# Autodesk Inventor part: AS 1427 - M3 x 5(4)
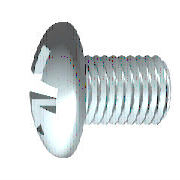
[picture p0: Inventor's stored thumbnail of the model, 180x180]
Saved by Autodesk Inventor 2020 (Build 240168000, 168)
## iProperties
Created: 2019-01
Part Number: AS 1427 - M3 x 5(4)
Material: Acier, doux
Description: Pozidriv Vis mécaniques métriques ISO
Document SubType Name: Modeling
Standard: AS 1427
Designer: bruno
Standards Organization: AS
Language: fr-FR
Size Designation: M3 x 5
Categories: <MemberInstance><Categories><Category DisplayName="Visserie" InternalName="e4da775c-781d-43d5-af7c-5136215cf5a6" Mnemonic="FSTN"><Category DisplayName="Vis" Int
Density: 7.85 g/cm^3
Appearance: Semi-poli
IsCustomPart: 0
Author: bruno
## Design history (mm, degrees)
body "Solid1"
workplane "Work Plane3"
sketch "Esquisse2"
  geometry: L1 (-4.2, 0)-(4.2, 0) reference; L2 (0, -4.2)-(0, 4.2) reference; L3 (0, 1.575)-(0, 0); L4 (0, 0)-(1.575, 0); L5 (0, 0)-(2.121, 2.121); L6 (0.35, 1.536)-(0.281, 0.474); L7 (1.536, 0.35)-(0.474, 0.281); L8 (0.35, -1.536)-(0.281, -0.474); L9 (1.536, -0.35)-(0.474, -0.281); L10 (-0.35, 1.536)-(-0.281, 0.474); L11 (-1.536, 0.35)-(-0.474, 0.281); L12 (-1.536, -0.35)-(-0.474, -0.281); L13 (-0.35, -1.536)-(-0.281, -0.474); A1 r 0.473 centre (0, 0) between (0.473, 0) and (0, 0.473); A2 r 1.575 centre (0, 0) between (1.575, 0) and (1.536, 0.35); A3 r 1.575 centre (0, 0) between (0.35, 1.536) and (0, 1.575); A4 r 1.575 centre (0, 0) between (1.536, 0.35) and (0.35, 1.536); A5 r 1.575 centre (0, 0) between (0, -1.575) and (0.35, -1.536); A6 r 1.575 centre (0, 0) between (0.35, -1.536) and (1.536, -0.35); A7 r 1.575 centre (0, 0) between (1.536, -0.35) and (1.575, 0); A8 r 1.575 centre (0, 0) between (-1.536, 0.35) and (-1.575, 0); A9 r 1.575 centre (0, 0) between (-0.35, 1.536) and (-1.536, 0.35); A10 r 1.575 centre (0, 0) between (0, 1.575) and (-0.35, 1.536); A11 r 1.575 centre (0, 0) between (-1.575, 0) and (-1.536, -0.35); A12 r 1.575 centre (0, 0) between (-1.536, -0.35) and (-0.35, -1.536); A13 r 1.575 centre (0, 0) between (-0.35, -1.536) and (0, -1.575); A14 r 0.551 centre (0, 0) between (0.551, 0) and (0, 0.551); A15 r 0.181 centre (0.462, 0.462) between (0.281, 0.474) and (0.474, 0.281); A16 r 0.181 centre (0.462, -0.462) between (0.474, -0.281) and (0.281, -0.474); A17 r 0.181 centre (-0.462, 0.462) between (-0.474, 0.281) and (-0.281, 0.474); A18 r 0.181 centre (-0.462, -0.462) between (-0.281, -0.474) and (-0.474, -0.281); 1 further point
  constraints: 38 point on circle, 22 end point, 19 symmetric about line, 18 centre point, 4 coincident, 3 collinear, 3 point on line, 3 tangent, 1 perpendicular, 21 other
  dimensions: "d4" = 45 deg angle of L5 L4; "d5" = 0.945 diameter of A1 (= 0.3 x SDM); "d6" = 3.15 diameter of A4 (= SDM); "d7" = 0.35 distance from line of L6.start L3 (= 0.5 x SBR); "d14" = 1.1025 diameter of A14 (= 0.35 x SDM)
extrude "Rainure" join sketch "Esquisse2" taper "d15" = 5 deg; stored distance "d54" = 10
revolve "Coupe" stored, may be unused: angle "d56" = 90 deg
revolve "Corps" stored, may be unused: angle "d18" = 90 deg
workplane "Work Plane1"
sketch "Esquisse1"
  geometry: L1 (5, 0)-(5, 1.5); L2 (5, 1.5)-(1, 1.5); L3 (3.962, 5.08)-(3.962, 5.08); L4 (-2.16, 0)-(-2.16, 3); L5 (-1.948, 1.47)-(-0.809, 0.902); L6 (-0.809, 0.902)-(-0.33, 0); L7 (-0.33, 0)-(5, 0); L8 (-3.87, 0)-(6.478, 0) reference; L9 (0, -1.016)-(0, 6.096) reference; L10 (-1.948, 1.47)-(-2.16, 1.575); L11 (-1.21, 3)-(-2.16, 3); L12 (-1.21, 3)-(0, 3); L13 (0, 3)-(0, 1.347); L14 (0, 1.347)-(0.693, 1.347); L15 (0.693, 1.347)-(1, 1.5); L16 (1, 1.5)-(0, 1.5); A1 r 5.21 centre (3.05, 0) between (-1.21, 3) and (-2.16, 0)
  constraints: 28 end point, 5 point on line, 4 collinear, 4 point on circle, 3 parallel, 2 perpendicular, 1 centre point, 1 horizontal, 1 tangent
  dimensions: "d1" = 3 diameter of L2 L7 (= GD); "d2" = 1.83 distance from line of L6.end L4 (= STI); "d11" = 3.15 diameter of L10.end L7 (= SDM); "d12" = 62 deg angle of L6 L7; "d13" = 26.5 deg angle of L5 L7; "d17" = 6 diameter of L12.end L7 (= KOD); "d19" = 0.01 deg angle of L12 L7 (= KEWI); "d20" = 2.16 distance between parallel lines of L4 L13 (= KOH); "d21" = 5.21 radius of A1 (= KR); "d23" = 2.6935 diameter of L14 L7 (= BDM); "d24" = 4 distance of L1.end L2.end (= GEL); "d25" = 0.30673 horizontal distance of L14.end L2.end (= GAL); "d28" = 5 distance between parallel lines of L1 L13 (= NLG)
fillet "Congé1" dims "d29" = 1.2 (= RR)
fillet "Congé2" dims "d16" = 0.14 (= 0.2 x SBR)
feature "Filetage" dims "d8" = 4 (= GEL), "d9" = 0
chamfer "Chanfrein1" distance "d26" = 0.30673 (= -0.5 x SPD + 0.5 x GD); stored, may be unused: second distance "d27" = 0.30683 (computed from GUL), angle "d78" = 45 deg
other parameters: "GD" = 3 (= NND) [user parameter; used in 2 equation terms], "NLG" = 5 [user parameter; used in 1 equation term], "GEL" = 4 [user parameter; used in 2 equation terms], "KOD" = 6 [user parameter; used in 1 equation term], "KOH" = 2.16 [user parameter; used in 2 equation terms], "SDM" = 3.15 [user parameter; used in 4 equation terms], "STI" = 1.83 [user parameter; used in 1 equation term], "SBR" = 0.7 [user parameter; used in 2 equation terms], "GAL" = 0.30673 (= 0.61345 x PTC) [user parameter; used in 1 equation term], "SPD" = 2.38655 (= NND - 1.2269 x PTC) [user parameter; used in 1 equation term], "KEWI" = 0.01 deg [user parameter; used in 1 equation term], "d3" = -2.16 (= -KOH), "d10" = 0, "KR" = 5.21 [user parameter; used in 1 equation term], "BDM" = 2.6935 [user parameter; used in 1 equation term], "GUL" = 0.30673 (= 0.61345 x PTC) [user parameter; used in 1 equation term], "RR" = 1.2 [user parameter; used in 1 equation term], "d79" = 0, "d80" = 0, "PTC" = 0.5 [user parameter; used in 5 equation terms], "THREADDIA" = 3 [user parameter; used in 1 equation term], "TOA" = 30 deg [user parameter], "NND" = 3 [user parameter; used in 2 equation terms], "GD1" = 2.38655 (= THREADDIA - 1.2269 x PTC) [user parameter]
